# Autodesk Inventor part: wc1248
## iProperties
Shininess: 64.0
Length Units: 11272
Angle Units: 11279
Time Units: 11290
Mass Units: 11286
Length Display Precision: 3
Angle Display Precision: 2
Compacted: True
Part Number: wc1248
Document SubType Name: Modeling
Created: 2004-08
Designer: John Blackburn
Manufacturer: Standard
Standards Organization: Custom
Density: 0.0
Volumn: 0.0
Area: 0.0
PropertySet Name: Model Information
Control State: 0
Master: False
Checked Out: False
Author: John Blackburn
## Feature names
1. Base1
